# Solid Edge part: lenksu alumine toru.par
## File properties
Title: lenksu alumine toru
Author: Stella-Marii
Template: iso metric part.par
Last saved by: Stella-Marii
Revision: 12
Application: Solid Edge
Document Number: 22
Density: 7833,000 kg/m^3
Accuracy: 0,990
Username: Stella-Marii
Material: Steel, structural
Face Style: Steel
Fill Style: ANSI32(Steel)
Virtual Style: Brushed steel
Grouping: Metals\Steel
LibraryName: Materials
Coef. of Thermal Exp: 1.3e-05
Thermal Conductivity: 32.0
Specific Heat: 481.0
Modulus of Elasticity: 199947953000.0
Poisson's Ratio: 0.29
Yield Stress: 262000766.0
Ultimate Stress: 358527364.0
Elongation: 0.0
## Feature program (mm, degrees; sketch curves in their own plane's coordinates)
sketch for "unnamed Protrusion 1" plane through (0, 0, 0) normal (0, 0, 1) x-axis (1, 0, 0)
  circle centre (0, 0) radius 22.5
extrude "unnamed Protrusion 1" add finite 50 along +normal
thinwall "Thinwall_1"  Thickness = 3 mm
sketch for "ExtrudedCutout_4" plane through (0, 0, 0) normal (0, -1, 0) x-axis (1, 0, 0)
extrude "ExtrudedCutout_4" cut finite 249.9887 symmetric
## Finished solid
Body 1: solid body, 5 faces, 6 edges, 0 vertices.
  Faces by surface: cylinder 3, plane 2
  Edges by curve: circle 4, intersection 2
Bounding box of the edges (mm): 45.000 x 45.000 x 50.000, from (-22.5, -22.5, 0) to (22.5, 22.5, 50).
Cylindrical faces by radius (mm): R12.5 x1, R19.5 x1, R22.5 x1
Planar faces by outward normal: +z 1, -z 1
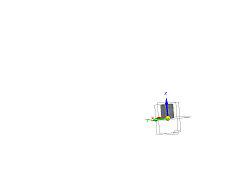
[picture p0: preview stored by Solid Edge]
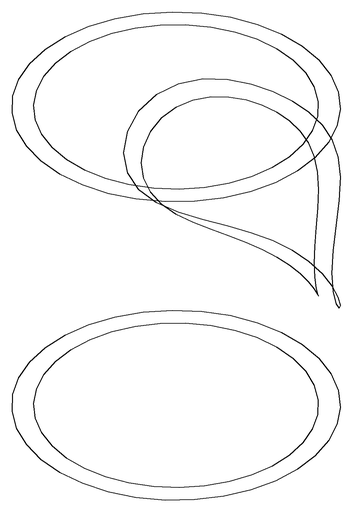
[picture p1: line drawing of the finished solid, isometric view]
